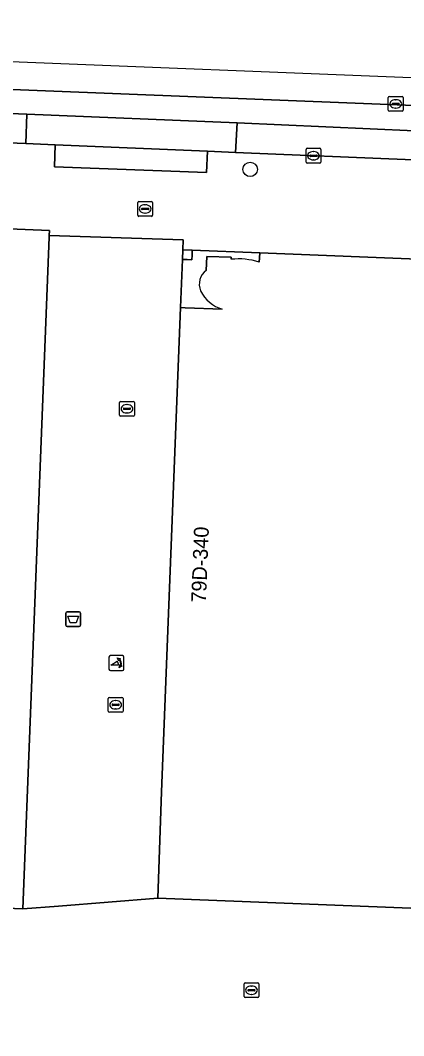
# Model space of a CAD drawing. Extents: x 160888 to 161385, y 386490 to 386908.
# Drawn here: x 161194.4 to 161220.3, y 386833.9 to 386902.4 of the extents above; entities that cross this region are included whole.
import ezdxf

# ---------------------------------------------------------------- set-up
doc = ezdxf.new("R2010")
doc.units = 0
for name, color, linetype in [('IMGEO_Afvalbak', 7, 'Continuous'), ('IMGEO_Boom', 7, 'Continuous'), ('IMGEO_Brandkraan', 7, 'Continuous'), ('IMGEO_Erf', 7, 'Continuous'), ('IMGEO_Hek', 7, 'Continuous'), ('IMGEO_Kolk', 7, 'Continuous'), ('IMGEO_Lage_trafo', 7, 'Continuous'), ('IMGEO_Pand', 7, 'Continuous'), ('IMGEO_Pand_nummerreeks', 7, 'Continuous'), ('IMGEO_Parkeervlak_gesloten', 7, 'Continuous'), ('IMGEO_Poller', 7, 'Continuous'), ('IMGEO_Rijbaan_lokaal_gesloten', 7, 'Continuous'), ('IMGEO_Rioolput', 7, 'Continuous'), ('IMGEO_Voetgangersgebied_open', 7, 'Continuous'), ('IMGEO_Voetpad_open', 7, 'Continuous')]:
    doc.layers.add(name, color=color, linetype=linetype)

msp = doc.modelspace()

# ---------------------------------------------------------------- linework, layer by layer
at = {"layer": 'IMGEO_Afvalbak'}
for p, q in [((161197.497, 386861.586), (161197.497, 386862.386)), ((161197.497, 386862.386), (161197.497, 386861.586)), ((161197.597, 386862.486), (161198.387, 386862.486)), ((161198.387, 386862.486), (161197.597, 386862.486)), ((161198.487, 386862.386), (161198.487, 386861.586)), ((161198.487, 386861.586), (161198.487, 386862.386)), ((161198.387, 386861.486), (161197.597, 386861.486)), ((161197.597, 386861.486), (161198.387, 386861.486))]:
    msp.add_line(p, q, dxfattribs=at)
msp.add_lwpolyline([(161197.64, 386862.2), (161198.344, 386862.2), (161198.195, 386861.73), (161197.789, 386861.73), (161197.64, 386862.2)], dxfattribs=at)
for centre, start, end in [((161197.597, 386862.386), 90, 180), ((161197.597, 386862.386), 90, 180), ((161198.387, 386862.386), 0, 90), ((161198.387, 386862.386), 360, 90), ((161197.597, 386861.586), 180, 270), ((161197.597, 386861.586), 180, 270), ((161198.387, 386861.586), 270, 0), ((161198.387, 386861.586), 270, 0)]:
    msp.add_arc(centre, 0.1, start, end, dxfattribs=at)
at = {"layer": 'IMGEO_Boom'}
msp.add_circle((161209.931, 386892.348), 0.489, dxfattribs=at)
at = {"layer": 'IMGEO_Brandkraan'}
for p, q in [((161202.346, 386889.252), (161202.346, 386890.104)), ((161202.421, 386890.178), (161203.273, 386890.178)), ((161203.347, 386890.104), (161203.347, 386889.252)), ((161202.605, 386889.672), (161202.605, 386889.684)), ((161203.043, 386889.635), (161202.645, 386889.635)), ((161202.648, 386889.721), (161203.046, 386889.721)), ((161202.834, 386889.958), (161202.859, 386889.958)), ((161203.089, 386889.684), (161203.089, 386889.672)), ((161203.273, 386889.178), (161202.421, 386889.178)), ((161202.857, 386889.398), (161202.832, 386889.398))]:
    msp.add_line(p, q, dxfattribs=at)
for points in [[(161202.346, 386889.252), (161202.346, 386890.104)], [(161202.421, 386890.178), (161203.273, 386890.178)], [(161203.347, 386890.104), (161203.347, 386889.252)], [(161203.273, 386889.178), (161202.421, 386889.178)]]:
    msp.add_lwpolyline(points, dxfattribs=at)
for centre, radius, start, end in [((161202.423, 386890.102), 0.0765, 91.55205, 178.44795), ((161202.423, 386890.102), 0.0765, 91.55205, 178.44795), ((161203.271, 386890.102), 0.0765, 1.55205, 88.44795), ((161203.271, 386890.102), 0.0765, 1.55205, 88.44795), ((161202.645, 386889.681), 0.0403, 85.87752, 175.75265), ((161202.642, 386889.671), 0.0366, 178.93798, 274.71019), ((161203.046, 386889.678), 0.043, 264.86636, 352.45326), ((161203.05, 386889.683), 0.0386, 1.73085, 96.63898), ((161202.423, 386889.254), 0.0765, 181.55205, 268.44795), ((161202.423, 386889.254), 0.0765, 181.55205, 268.44795), ((161203.271, 386889.254), 0.0765, 271.55205, 358.44795), ((161203.271, 386889.254), 0.0765, 271.55205, 358.44795)]:
    msp.add_arc(centre, radius, start, end, dxfattribs=at)
for centre, major_axis, ratio, start_param, end_param in [((161202.833, 386889.678), (-0.387, 0.002), 0.722429, 4.712389, 7.853982), ((161202.858, 386889.678), (-0.39, 0.002), 0.717154, 1.570796, 4.712389)]:
    msp.add_ellipse(centre, major_axis=major_axis, ratio=ratio, start_param=start_param, end_param=end_param, dxfattribs=at)
at = {"layer": 'IMGEO_Erf'}
for points in [[(161210.538, 386886.09), (161210.559, 386886.386), (161210.581, 386886.706), (161206.029, 386886.888), (161206.017, 386886.568), (161206.004, 386886.249), (161205.681, 386886.26), (161205.361, 386886.272), (161205.23, 386883.017), (161205.549, 386883.004), (161208.047, 386882.906)], [(161206.97, 386885.531), (161207.007, 386886.478), (161208.657, 386886.418), (161208.652, 386886.278)]]:
    msp.add_lwpolyline(points, dxfattribs=at)
for centre, radius, start, end in [((161209.138, 386881.603), 4.701, 72.67666, 95.93825), ((161207.669, 386884.592), 1.171, 126.67252, 202.31343), ((161208.783, 386885.253), 2.46, 206.72065, 252.58899)]:
    msp.add_arc(centre, radius, start, end, dxfattribs=at)
at = {"layer": 'IMGEO_Hek'}
msp.add_lwpolyline([(161196.381, 386887.886), (161205.414, 386887.602), (161205.385, 386886.913)], dxfattribs=at)
at = {"layer": 'IMGEO_Kolk'}
for p, q in [((161213.701, 386892.843), (161213.701, 386893.695)), ((161213.776, 386893.769), (161214.628, 386893.769)), ((161214.189, 386893.549), (161214.214, 386893.549)), ((161214.702, 386893.695), (161214.702, 386892.843)), ((161213.96, 386893.263), (161213.96, 386893.275)), ((161214.398, 386893.226), (161214, 386893.226)), ((161214.003, 386893.312), (161214.401, 386893.312)), ((161214.212, 386892.989), (161214.187, 386892.989)), ((161214.444, 386893.275), (161214.444, 386893.263)), ((161214.628, 386892.769), (161213.776, 386892.769)), ((161201.118, 386875.762), (161201.118, 386876.614)), ((161201.193, 386876.688), (161202.045, 386876.688)), ((161201.606, 386876.468), (161201.631, 386876.468)), ((161202.119, 386876.614), (161202.119, 386875.762)), ((161201.377, 386876.182), (161201.377, 386876.194)), ((161201.815, 386876.145), (161201.417, 386876.145)), ((161201.42, 386876.231), (161201.818, 386876.231)), ((161201.629, 386875.908), (161201.604, 386875.908)), ((161201.861, 386876.194), (161201.861, 386876.182)), ((161202.045, 386875.688), (161201.193, 386875.688)), ((161200.357, 386855.781), (161200.357, 386856.633)), ((161200.432, 386856.707), (161201.284, 386856.707)), ((161201.358, 386856.633), (161201.358, 386855.781)), ((161200.616, 386856.201), (161200.616, 386856.213)), ((161201.054, 386856.164), (161200.656, 386856.164)), ((161200.659, 386856.25), (161201.057, 386856.25)), ((161200.868, 386855.927), (161200.843, 386855.927)), ((161200.845, 386856.487), (161200.87, 386856.487)), ((161201.1, 386856.213), (161201.1, 386856.201)), ((161201.284, 386855.707), (161200.432, 386855.707)), ((161209.516, 386836.517), (161209.516, 386837.369)), ((161209.591, 386837.443), (161210.443, 386837.443)), ((161210.517, 386837.369), (161210.517, 386836.517)), ((161209.775, 386836.937), (161209.775, 386836.949)), ((161210.213, 386836.9), (161209.815, 386836.9)), ((161209.818, 386836.986), (161210.216, 386836.986)), ((161210.027, 386836.663), (161210.002, 386836.663)), ((161210.004, 386837.223), (161210.029, 386837.223)), ((161210.259, 386836.949), (161210.259, 386836.937)), ((161210.443, 386836.443), (161209.591, 386836.443))]:
    msp.add_line(p, q, dxfattribs=at)
for points in [[(161213.701, 386892.843), (161213.701, 386893.695)], [(161213.776, 386893.769), (161214.628, 386893.769)], [(161214.702, 386893.695), (161214.702, 386892.843)], [(161214.628, 386892.769), (161213.776, 386892.769)], [(161201.118, 386875.762), (161201.118, 386876.614)], [(161201.193, 386876.688), (161202.045, 386876.688)], [(161202.119, 386876.614), (161202.119, 386875.762)], [(161202.045, 386875.688), (161201.193, 386875.688)], [(161200.357, 386855.781), (161200.357, 386856.633)], [(161200.432, 386856.707), (161201.284, 386856.707)], [(161201.358, 386856.633), (161201.358, 386855.781)], [(161201.284, 386855.707), (161200.432, 386855.707)], [(161209.516, 386836.517), (161209.516, 386837.369)], [(161209.591, 386837.443), (161210.443, 386837.443)], [(161210.517, 386837.369), (161210.517, 386836.517)], [(161210.443, 386836.443), (161209.591, 386836.443)]]:
    msp.add_lwpolyline(points, dxfattribs=at)
for centre, radius, start, end in [((161213.778, 386893.693), 0.0765, 91.55205, 178.44795), ((161213.778, 386893.693), 0.0765, 91.55205, 178.44795), ((161214.626, 386893.693), 0.0765, 1.55205, 88.44795), ((161214.626, 386893.693), 0.0765, 1.55205, 88.44795), ((161214, 386893.272), 0.0403, 85.87752, 175.75265), ((161213.997, 386893.262), 0.0366, 178.93798, 274.71019), ((161214.401, 386893.269), 0.043, 264.86636, 352.45326), ((161214.405, 386893.274), 0.0386, 1.73085, 96.63898), ((161213.778, 386892.845), 0.0765, 181.55205, 268.44795), ((161213.778, 386892.845), 0.0765, 181.55205, 268.44795), ((161214.626, 386892.845), 0.0765, 271.55205, 358.44795), ((161214.626, 386892.845), 0.0765, 271.55205, 358.44795), ((161201.195, 386876.612), 0.0765, 91.55205, 178.44795), ((161201.195, 386876.612), 0.0765, 91.55205, 178.44795), ((161202.043, 386876.612), 0.0765, 1.55205, 88.44795), ((161202.043, 386876.612), 0.0765, 1.55205, 88.44795), ((161201.195, 386875.764), 0.0765, 181.55205, 268.44795), ((161201.195, 386875.764), 0.0765, 181.55205, 268.44795), ((161201.417, 386876.191), 0.0403, 85.87752, 175.75265), ((161201.414, 386876.181), 0.0366, 178.93798, 274.71019), ((161201.818, 386876.188), 0.043, 264.86636, 352.45326), ((161201.822, 386876.193), 0.0386, 1.73085, 96.63898), ((161202.043, 386875.764), 0.0765, 271.55205, 358.44795), ((161202.043, 386875.764), 0.0765, 271.55205, 358.44795), ((161200.434, 386856.631), 0.0765, 91.55205, 178.44795), ((161200.434, 386856.631), 0.0765, 91.55205, 178.44795), ((161201.282, 386856.631), 0.0765, 1.55205, 88.44795), ((161201.282, 386856.631), 0.0765, 1.55205, 88.44795), ((161200.656, 386856.21), 0.0403, 85.87752, 175.75265), ((161200.653, 386856.2), 0.0366, 178.93798, 274.71019), ((161201.057, 386856.207), 0.043, 264.86636, 352.45326), ((161201.061, 386856.212), 0.0386, 1.73085, 96.63898), ((161200.434, 386855.783), 0.0765, 181.55205, 268.44795), ((161200.434, 386855.783), 0.0765, 181.55205, 268.44795), ((161201.282, 386855.783), 0.0765, 271.55205, 358.44795), ((161201.282, 386855.783), 0.0765, 271.55205, 358.44795), ((161209.593, 386837.367), 0.0765, 91.55205, 178.44795), ((161209.593, 386837.367), 0.0765, 91.55205, 178.44795), ((161210.441, 386837.367), 0.0765, 1.55205, 88.44795), ((161210.441, 386837.367), 0.0765, 1.55205, 88.44795), ((161209.815, 386836.946), 0.0403, 85.87752, 175.75265), ((161209.812, 386836.936), 0.0366, 178.93798, 274.71019), ((161210.216, 386836.943), 0.043, 264.86636, 352.45326), ((161210.22, 386836.948), 0.0386, 1.73085, 96.63898), ((161209.593, 386836.519), 0.0765, 181.55205, 268.44795), ((161209.593, 386836.519), 0.0765, 181.55205, 268.44795), ((161210.441, 386836.519), 0.0765, 271.55205, 358.44795), ((161210.441, 386836.519), 0.0765, 271.55205, 358.44795)]:
    msp.add_arc(centre, radius, start, end, dxfattribs=at)
for centre, major_axis, ratio, start_param, end_param in [((161214.188, 386893.269), (-0.387, 0.002), 0.722429, 4.712389, 7.853982), ((161214.213, 386893.269), (-0.39, 0.002), 0.717154, 1.570796, 4.712389), ((161201.605, 386876.188), (-0.387, 0.002), 0.722429, 4.712389, 7.853982), ((161201.63, 386876.188), (-0.39, 0.002), 0.717154, 1.570796, 4.712389), ((161200.844, 386856.207), (-0.387, 0.002), 0.722429, 4.712389, 7.853982), ((161200.869, 386856.207), (-0.39, 0.002), 0.717154, 1.570796, 4.712389), ((161210.003, 386836.943), (-0.387, 0.002), 0.722429, 4.712389, 7.853982), ((161210.028, 386836.943), (-0.39, 0.002), 0.717154, 1.570796, 4.712389)]:
    msp.add_ellipse(centre, major_axis=major_axis, ratio=ratio, start_param=start_param, end_param=end_param, dxfattribs=at)
at = {"layer": 'IMGEO_Lage_trafo'}
msp.add_lwpolyline([(161205.385, 386886.913), (161205.361, 386886.272), (161205.681, 386886.26), (161206.004, 386886.249), (161206.017, 386886.568), (161206.029, 386886.888)], close=True, dxfattribs=at)
at = {"layer": 'IMGEO_Pand'}
msp.add_lwpolyline([(161120.067, 386845.369), (161194.586, 386842.427), (161196.377, 386887.78), (161196.381, 386887.886), (161196.395, 386888.23), (161188.186, 386888.554), (161178.427, 386888.94), (161127.058, 386890.969), (161126.941, 386888.577), (161126.862, 386886.972), (161123.715, 386887.092), (161123.545, 386882.788), (161121.567, 386882.869), (161121.073, 386870.746), (161120.711, 386870.76), (161120.682, 386870.014), (161121.042, 386870), (161120.551, 386857.609)], close=True, dxfattribs=at)
for points in [[(161238.86, 386863.105), (161238.505, 386854.269), (161229.279, 386854.644), (161221.919, 386854.943), (161221.965, 386856.062), (161221.271, 386856.091), (161221.066, 386856.099), (161221.078, 386856.403), (161221.275, 386860.943), (161221.375, 386860.939), (161222.369, 386886.248), (161210.581, 386886.706), (161210.559, 386886.386), (161210.538, 386886.09)], [(161208.652, 386886.278), (161208.657, 386886.418), (161207.007, 386886.478), (161206.97, 386885.531)], [(161208.047, 386882.906), (161205.549, 386883.004), (161205.23, 386883.017), (161203.943, 386850.322), (161203.707, 386843.159), (161282.19, 386840.045), (161283.986, 386839.974), (161284.468, 386852.014), (161284.901, 386852.005), (161284.908, 386852.43), (161283.395, 386852.488), (161277.385, 386852.718), (161277.574, 386857.417), (161267.493, 386857.839), (161267.366, 386854.695), (161257.979, 386855.044), (161254.641, 386855.168), (161254.804, 386859.3), (161254.82, 386859.706), (161248.886, 386860.967), (161238.86, 386863.105)]]:
    msp.add_lwpolyline(points, dxfattribs=at)
for centre, radius, start, end in [((161209.138, 386881.603), 4.701, 72.67666, 95.93825), ((161207.669, 386884.592), 1.171, 126.67252, 202.31343), ((161208.783, 386885.253), 2.46, 206.72065, 252.58899)]:
    msp.add_arc(centre, radius, start, end, dxfattribs=at)
at = {"layer": 'IMGEO_Parkeervlak_gesloten'}
for points in [[(161194.86, 386896.072), (161176.778, 386896.8), (161176.703, 386894.8), (161194.801, 386894.087)], [(161221.008, 386894.938), (161209.056, 386895.484), (161208.945, 386893.49), (161220.937, 386892.996)]]:
    msp.add_lwpolyline(points, close=True, dxfattribs=at)
at = {"layer": 'IMGEO_Poller'}
for p, q in [((161200.408, 386859.43), (161200.408, 386858.623)), ((161200.408, 386859.43), (161200.408, 386858.623)), ((161201.31, 386859.525), (161200.502, 386859.525)), ((161201.31, 386859.525), (161200.502, 386859.525)), ((161201.404, 386858.623), (161201.404, 386859.43)), ((161201.404, 386858.623), (161201.404, 386859.43)), ((161200.502, 386858.528), (161201.31, 386858.528)), ((161200.502, 386858.528), (161201.31, 386858.528))]:
    msp.add_line(p, q, dxfattribs=at)
for points in [[(161201.087, 386859.254), (161201.075, 386859.181), (161200.95, 386859.386)], [(161200.95, 386859.386), (161201.181, 386859.32), (161201.11, 386859.288)], [(161201.043, 386858.881), (161200.53, 386858.881), (161200.96, 386859.156)], [(161201.103, 386858.709), (161201.169, 386858.94), (161201.199, 386858.872)], [(161201.235, 386858.845), (161201.307, 386858.834), (161201.103, 386858.709)]]:
    msp.add_lwpolyline(points, dxfattribs=at)
for centre, radius, start, end in [((161200.502, 386859.43), 0.0946, 90, 180), ((161200.502, 386859.43), 0.0946, 90, 180), ((161200.729, 386858.941), 0.516, 349.35686, 42.29123), ((161201.31, 386859.43), 0.0946, 0, 90), ((161201.31, 386859.43), 0.0946, 0, 90), ((161200.502, 386858.623), 0.0946, 180, 270), ((161200.502, 386858.623), 0.0946, 180, 270), ((161200.715, 386858.931), 0.332, 351.32473, 42.4854), ((161200.729, 386858.941), 0.476, 351.75274, 41.16905), ((161201.31, 386858.623), 0.0946, 270, 0), ((161201.31, 386858.623), 0.0946, 270, 0)]:
    msp.add_arc(centre, radius, start, end, dxfattribs=at)
at = {"layer": 'IMGEO_Rijbaan_lokaal_gesloten'}
msp.add_lwpolyline([(161291.165, 386895.721), (161123.374, 386902.409), (161123.263, 386900.56), (161248.069, 386895.57), (161278.544, 386894.358), (161279.11, 386894.349), (161286.088, 386894.243)], dxfattribs=at)
for points in [[(161279.11, 386894.349), (161278.544, 386894.358), (161248.069, 386895.57), (161123.263, 386900.56), (161123.188, 386898.901), (161155.904, 386897.594), (161176.778, 386896.8), (161194.86, 386896.072), (161209.056, 386895.484), (161221.008, 386894.938), (161241.882, 386894.123), (161247.927, 386893.867), (161258.887, 386893.342), (161276.971, 386892.717), (161277.593, 386892.717), (161277.832, 386892.705), (161279.059, 386892.659)], [(161209.056, 386895.484), (161194.86, 386896.072), (161194.801, 386894.087), (161196.781, 386894.009), (161207.063, 386893.567), (161208.945, 386893.49)]]:
    msp.add_lwpolyline(points, close=True, dxfattribs=at)
at = {"layer": 'IMGEO_Rioolput'}
for p, q in [((161219.251, 386896.342), (161219.251, 386897.194)), ((161219.326, 386897.268), (161220.178, 386897.268)), ((161219.739, 386897.048), (161219.764, 386897.048)), ((161220.252, 386897.194), (161220.252, 386896.342)), ((161219.51, 386896.762), (161219.51, 386896.774)), ((161219.948, 386896.725), (161219.55, 386896.725)), ((161219.553, 386896.811), (161219.951, 386896.811)), ((161219.762, 386896.488), (161219.737, 386896.488)), ((161219.994, 386896.774), (161219.994, 386896.762)), ((161220.178, 386896.268), (161219.326, 386896.268))]:
    msp.add_line(p, q, dxfattribs=at)
for points in [[(161219.251, 386896.342), (161219.251, 386897.194)], [(161219.326, 386897.268), (161220.178, 386897.268)], [(161220.252, 386897.194), (161220.252, 386896.342)], [(161220.178, 386896.268), (161219.326, 386896.268)]]:
    msp.add_lwpolyline(points, dxfattribs=at)
for centre, radius, start, end in [((161219.328, 386897.192), 0.0765, 91.55205, 178.44795), ((161219.328, 386897.192), 0.0765, 91.55205, 178.44795), ((161220.176, 386897.192), 0.0765, 1.55205, 88.44795), ((161220.176, 386897.192), 0.0765, 1.55205, 88.44795), ((161219.328, 386896.344), 0.0765, 181.55205, 268.44795), ((161219.328, 386896.344), 0.0765, 181.55205, 268.44795), ((161219.55, 386896.771), 0.0403, 85.87752, 175.75265), ((161219.547, 386896.761), 0.0366, 178.93798, 274.71019), ((161219.951, 386896.768), 0.043, 264.86636, 352.45326), ((161219.955, 386896.773), 0.0386, 1.73085, 96.63898), ((161220.176, 386896.344), 0.0765, 271.55205, 358.44795), ((161220.176, 386896.344), 0.0765, 271.55205, 358.44795)]:
    msp.add_arc(centre, radius, start, end, dxfattribs=at)
for centre, major_axis, ratio, start_param, end_param in [((161219.738, 386896.768), (-0.387, 0.002), 0.722429, 4.712389, 7.853982), ((161219.763, 386896.768), (-0.39, 0.002), 0.717154, 1.570796, 4.712389)]:
    msp.add_ellipse(centre, major_axis=major_axis, ratio=ratio, start_param=start_param, end_param=end_param, dxfattribs=at)
at = {"layer": 'IMGEO_Voetgangersgebied_open'}
msp.add_lwpolyline([(161205.23, 386883.017), (161205.361, 386886.272), (161205.385, 386886.913), (161205.414, 386887.602), (161196.381, 386887.886), (161196.377, 386887.78), (161194.586, 386842.427), (161196.993, 386842.62), (161203.707, 386843.159), (161203.943, 386850.322)], close=True, dxfattribs=at)
msp.add_lwpolyline([(161128.442, 386835.301), (161139.684, 386834.849), (161143.958, 386834.674), (161161.282, 386833.963), (161170.867, 386833.628), (161190.117, 386832.93), (161199.627, 386832.585), (161199.621, 386832.448), (161201.804, 386832.359), (161216.339, 386831.766), (161223.504, 386831.473), (161238.036, 386830.88), (161252.467, 386830.291), (161259.736, 386829.994), (161269.188, 386829.608), (161281.723, 386829.096), (161281.825, 386831.496), (161282.087, 386837.641), (161282.13, 386838.652), (161282.19, 386840.045), (161203.707, 386843.159), (161196.993, 386842.62), (161194.586, 386842.427), (161120.067, 386845.369)], dxfattribs=at)
at = {"layer": 'IMGEO_Voetpad_open'}
for points in [[(161274.2, 386890.804), (161258.81, 386891.423), (161256.885, 386891.501), (161256.805, 386890.402), (161250.217, 386890.662), (161250.255, 386891.79), (161247.831, 386891.89), (161241.794, 386892.138), (161239.425, 386892.236), (161239.41, 386891.107), (161235.397, 386891.29), (161235.468, 386892.398), (161220.937, 386892.996), (161208.945, 386893.49), (161207.063, 386893.567), (161206.996, 386892.136), (161196.74, 386892.515), (161196.781, 386894.009), (161194.801, 386894.087), (161176.703, 386894.8), (161176.66, 386894.802), (161176.601, 386893.617), (161155.57, 386894.474), (161155.616, 386895.637)], [(161127.058, 386890.969), (161178.427, 386888.94), (161188.186, 386888.554), (161196.395, 386888.23), (161196.381, 386887.886), (161205.414, 386887.602), (161205.385, 386886.913), (161206.029, 386886.888), (161210.581, 386886.706), (161222.369, 386886.248), (161222.396, 386887.248), (161239.793, 386886.567), (161249.896, 386886.171), (161268.594, 386885.414), (161278.689, 386885.003), (161279.034, 386891.63), (161279.059, 386892.659), (161277.832, 386892.705), (161277.593, 386892.717)]]:
    msp.add_lwpolyline(points, dxfattribs=at)
msp.add_lwpolyline([(161207.063, 386893.567), (161196.781, 386894.009), (161196.74, 386892.515), (161206.996, 386892.136)], close=True, dxfattribs=at)

# ---------------------------------------------------------------- texts
at = {"layer": 'IMGEO_Pand_nummerreeks'}
msp.add_text('79D-340', height=1, rotation=87.74849, dxfattribs=at).set_placement((161206.948, 386863.088))

doc.saveas('drawing.dxf')
